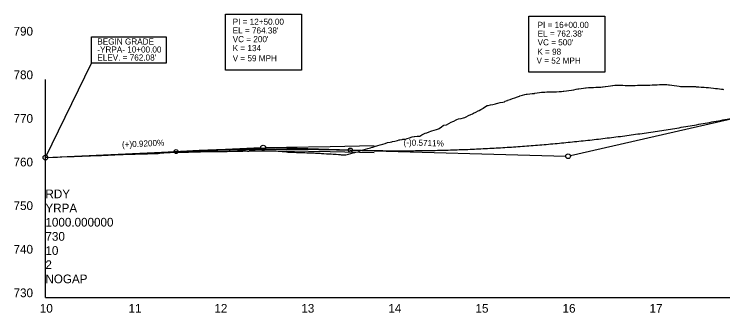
# Model space of a CAD drawing. Extents: x 579185 to 595036, y -53221 to -44640.
# Drawn here: x 579251 to 580065, y -52480 to -52138 of the extents above; entities that cross this region are included whole.
import ezdxf

# ---------------------------------------------------------------- set-up
doc = ezdxf.new("R2010")
doc.units = 0
for name, color, linetype in [('Default', 7, 'Continuous'), ('Exist Profile Cell', 7, 'Continuous'), ('Exist Vertical Profile Ground Line', 7, 'Continuous'), ('Exist Vertical Profile Horizontal Axis Label Major', 7, 'Continuous'), ('Exist Vertical Profile Vertical Axis Label', 7, 'Continuous'), ('Prop Grid Mask', 7, 'Continuous'), ('Prop Vertical Profile Curve Label', 7, 'Continuous'), ('Prop Vertical Profile Grade', 7, 'Continuous'), ('Prop Vertical Profile Grade Label', 7, 'Continuous'), ('Prop VPI Label', 7, 'Continuous')]:
    doc.layers.add(name, color=color, linetype=linetype)

msp = doc.modelspace()

# ---------------------------------------------------------------- linework, layer by layer
at = {"layer": 'Default'}
for points in [[(579287.34, -52302.25), (579314.37, -52300.95), (579364.23, -52298.74), (579414.11, -52296.26), (579464.01, -52293.7), (579513.93, -52291.66), (579563.95, -52290.5), (579614.16, -52289.59), (579664.7, -52288.43)], [(579287.34, -52302.25), (579314.37, -52300.95), (579364.23, -52298.74), (579414.11, -52296.95), (579464.01, -52295.52), (579513.93, -52294.72), (579563.95, -52294.55), (579614.16, -52295.18), (579664.7, -52296.48)]]:
    msp.add_lwpolyline(points, dxfattribs=at)
at = {"layer": 'Exist Profile Cell'}
for q in [(579287.34, -52212.63), (580953.86, -52462.63), (579287.34, -52462.63)]:
    msp.add_line((579287.34, -52462.63), q, dxfattribs=at)
at = {"layer": 'Exist Vertical Profile Ground Line'}
for points in [[(579739.22, -52268.87), (579742.03, -52266.83), (579743.91, -52265.47), (579744.84, -52265.25), (579747.73, -52264.58), (579750.47, -52263.2), (579753.28, -52261.77), (579755.08, -52260.85), (579756.09, -52260.34), (579758.91, -52258.9), (579759.63, -52258.53), (579761.72, -52258.01), (579764.53, -52257.32), (579767.34, -52256.61), (579768.67, -52256.28), (579770.16, -52255.56), (579772.97, -52254.19), (579775.78, -52252.82), (579777.63, -52251.92), (579778.59, -52251.46), (579781.41, -52250.12), (579784.22, -52248.78), (579785.14, -52248.34), (579787.03, -52247.27), (579789.39, -52245.93), (579789.85, -52245.64), (579792.66, -52243.82), (579794.37, -52242.7), (579795.47, -52242.46), (579798.28, -52241.84), (579801.1, -52241.22), (579803.91, -52240.61), (579805.29, -52240.31), (579806.72, -52239.96), (579809.53, -52239.28), (579812.35, -52238.61), (579814.21, -52238.16), (579815.16, -52237.75), (579817.63, -52236.7), (579817.97, -52236.58), (579820.78, -52235.59), (579823.6, -52234.59), (579826.41, -52233.59), (579829.22, -52232.59), (579831.58, -52231.75), (579832.03, -52231.62), (579834.85, -52230.85), (579837.66, -52230.07), (579839.04, -52229.69), (579840.47, -52229.53), (579843.28, -52229.23), (579846.1, -52228.93), (579848.91, -52228.62), (579849.31, -52228.58), (579851.72, -52228.17), (579854.53, -52227.7), (579856.74, -52227.33), (579857.35, -52227.29), (579860.16, -52227.12), (579860.64, -52227.09), (579862.97, -52227.05), (579865.79, -52227), (579868.6, -52226.95), (579869.73, -52226.93), (579871.41, -52226.85), (579874.22, -52226.71), (579877.04, -52226.57), (579877.86, -52226.53), (579879.85, -52226.38), (579881.67, -52226.25), (579882.66, -52226.11), (579885.47, -52225.72), (579888.29, -52225.32), (579891.1, -52224.93), (579893.43, -52224.61), (579893.91, -52224.5), (579896.72, -52223.87), (579898.6, -52223.45), (579899.54, -52223.32), (579902.35, -52222.92), (579905.16, -52222.52), (579907.37, -52222.2), (579907.97, -52222.18), (579910.79, -52222.05), (579913.6, -52221.92), (579916.41, -52221.8), (579919.22, -52221.67), (579922.09, -52221.54), (579924.85, -52221.37), (579926.8, -52221.24), (579927.66, -52221.14), (579930.1, -52220.87), (579930.47, -52220.81), (579933.29, -52220.34), (579936.1, -52219.88), (579938.37, -52219.5), (579938.91, -52219.45), (579940.97, -52219.24), (579941.72, -52219.21), (579942.2, -52219.19), (579944.54, -52219.25)], [(579944.54, -52219.25), (579947.35, -52219.31), (579950.16, -52219.37), (579952.98, -52219.43), (579955.79, -52219.49), (579957.21, -52219.53), (579958.6, -52219.51), (579961.41, -52219.46), (579964.23, -52219.42), (579967.04, -52219.38), (579969.85, -52219.33), (579972.66, -52219.29), (579975.48, -52219.24), (579977.49, -52219.21), (579978.29, -52219.18), (579981.1, -52219.06), (579983.91, -52218.95), (579986.73, -52218.83), (579989.54, -52218.72), (579992.35, -52218.61), (579995.16, -52218.49), (579997.98, -52218.38), (579998.43, -52218.36), (580000.79, -52218.31), (580002.75, -52218.88), (580003.6, -52218.98), (580006.41, -52219.33), (580009.23, -52219.67), (580012.04, -52220.02), (580014.85, -52220.36), (580016.54, -52220.57), (580017.66, -52220.59), (580020.48, -52220.64), (580023.29, -52220.69), (580026.1, -52220.75), (580028.92, -52220.8), (580031.73, -52220.86), (580033.44, -52220.89), (580034.54, -52220.96), (580037.35, -52221.14), (580040.17, -52221.32), (580042.98, -52221.51), (580043.63, -52221.55), (580045.79, -52221.78), (580048.6, -52222.08), (580051.42, -52222.38), (580054.23, -52222.68), (580056.57, -52222.93), (580058.92, -52223.18), (580061.26, -52223.43), (580063.6, -52223.68), (580064.89, -52223.82), (580065.95, -52224.06)], [(579533.43, -52294.64), (579535.78, -52294.63), (579538.12, -52294.62), (579540.46, -52294.61), (579542.81, -52294.6), (579545.15, -52294.6), (579546.87, -52294.6), (579547.5, -52294.59), (579549.84, -52294.55), (579550.71, -52294.53), (579552.18, -52294.61), (579554.53, -52294.74), (579555.83, -52294.81), (579556.87, -52294.92), (579559.21, -52295.17), (579561.56, -52295.43), (579563.9, -52295.69), (579565.66, -52295.89), (579566.25, -52295.91), (579568.59, -52296.01), (579570.93, -52296.1), (579573.35, -52296.21), (579575.62, -52296.27), (579577.96, -52296.34), (579580.31, -52296.41), (579582.65, -52296.48), (579585, -52296.56), (579587.34, -52296.65), (579590.15, -52296.75), (579592.96, -52296.86), (579595.78, -52296.98), (579597.4, -52297.05), (579598.59, -52297.11), (579601.4, -52297.24), (579602.26, -52297.28), (579602.64, -52297.35), (579604.21, -52297.45), (579606.39, -52297.58), (579607.03, -52297.62), (579609.84, -52297.78), (579612.65, -52297.95), (579615.46, -52298.12), (579617.69, -52298.26), (579618.28, -52298.3), (579621.09, -52298.51), (579623.9, -52298.72), (579625.6, -52298.86), (579626.72, -52298.92), (579629.53, -52299.09), (579632.34, -52299.24), (579635.15, -52298.46), (579637.97, -52297.66), (579640.78, -52296.86), (579642.69, -52296.31), (579643.59, -52296.16), (579646.4, -52295.68), (579649.22, -52294.25), (579649.74, -52293.99), (579652.03, -52293.38), (579654.84, -52292.62), (579657.65, -52291.85), (579660.47, -52291.07), (579662.59, -52290.47), (579663.28, -52290.26), (579666.09, -52289.36), (579667.76, -52288.83), (579668.9, -52288.49), (579671.72, -52287.66), (579674.53, -52286.82), (579677.34, -52285.97), (579680.15, -52285.11), (579682.97, -52284.58), (579684.83, -52284.21), (579685.78, -52283.99), (579688.59, -52283.3), (579691.4, -52282.6), (579693.56, -52282.06), (579694.22, -52281.93), (579697.03, -52281.41), (579697.65, -52281.29), (579699.84, -52281.05), (579700.57, -52280.97), (579702.66, -52280.34), (579705.47, -52279.48), (579708.28, -52278.61), (579710.47, -52277.94), (579711.09, -52277.9), (579713.91, -52277.73), (579716.72, -52277.56), (579717.04, -52277.54), (579719.53, -52276.23), (579722.34, -52274.78), (579723.47, -52274.32), (579725.16, -52273.86), (579727.97, -52272.71), (579729.81, -52271.94), (579730.78, -52271.66), (579733.59, -52270.85), (579736.41, -52270.02), (579738.48, -52269.41), (579739.22, -52268.87)], [(579287.34, -52302.25), (579296.71, -52301.82), (579298.51, -52301.73), (579301.13, -52301.62), (579306.09, -52301.43), (579315.46, -52301.07), (579318.71, -52300.95), (579320.15, -52300.89), (579324.84, -52300.71), (579326.21, -52300.66), (579329.53, -52300.53), (579334.21, -52300.36), (579338.96, -52300.18), (579343.59, -52300), (579348.28, -52299.83), (579351.77, -52299.69), (579352.96, -52299.65), (579357.65, -52299.46), (579359.54, -52299.39), (579362.34, -52299.28), (579367.03, -52299.09), (579371.71, -52298.91), (579375.87, -52298.75), (579376.4, -52298.72), (579381.09, -52298.53), (579385.78, -52298.35), (579388.2, -52298.25), (579390.46, -52298.16), (579395.15, -52297.99), (579397.5, -52297.88), (579398.17, -52297.8), (579400.13, -52297.92), (579402.18, -52297.86), (579404.53, -52297.8), (579406.87, -52297.74), (579409.21, -52297.67), (579411.56, -52297.61), (579413.9, -52297.55), (579416.25, -52297.5), (579416.64, -52297.49), (579418.59, -52297.22), (579420.93, -52296.91), (579421.97, -52296.77), (579423.28, -52296.63), (579425.66, -52296.37), (579427.96, -52296.25), (579430.31, -52296.13), (579432.65, -52296.01), (579434.62, -52295.91), (579435, -52295.91), (579437.34, -52295.92), (579439.68, -52295.92), (579442.03, -52295.93), (579443.39, -52295.93), (579444.37, -52295.93), (579446.71, -52295.92), (579449.06, -52295.91), (579449.84, -52295.91), (579451.4, -52295.88), (579453.75, -52295.83), (579456.09, -52295.79), (579458.43, -52295.74), (579459.05, -52295.73), (579460.78, -52295.68), (579463.12, -52295.6), (579465.46, -52295.53), (579467.81, -52295.46), (579469.64, -52295.4), (579470.15, -52295.4), (579472.5, -52295.4), (579474.84, -52295.39), (579477.18, -52295.39), (579479.53, -52295.39), (579481.87, -52295.39), (579484.21, -52295.39), (579486.56, -52295.4), (579486.95, -52295.4), (579489.15, -52295.36), (579491.25, -52295.29), (579493.59, -52295.23), (579493.99, -52295.22), (579495.93, -52295.13), (579498.28, -52295.03), (579500.62, -52294.92), (579502.96, -52294.82), (579505.31, -52294.72), (579507.65, -52294.62), (579510, -52294.52), (579510.55, -52294.5), (579512.34, -52294.54), (579514.68, -52294.61), (579517.03, -52294.67), (579519.37, -52294.73), (579520.4, -52294.76), (579521.71, -52294.31), (579524.26, -52293.54), (579526.4, -52293.94), (579528.75, -52294.38), (579530.22, -52294.66), (579531.09, -52294.65), (579533.43, -52294.64)]]:
    msp.add_lwpolyline(points, dxfattribs=at)
at = {"layer": 'Prop Grid Mask'}
for points in [[(579493.95, -52137.82), (579581.31, -52137.82), (579581.31, -52202), (579493.95, -52202)], [(579842.22, -52140.24), (579929.58, -52140.24), (579929.58, -52204.42), (579842.22, -52204.42)], [(579340.36, -52163.89), (579425.76, -52163.89), (579425.76, -52194.08), (579340.36, -52194.08)]]:
    msp.add_lwpolyline(points, close=True, dxfattribs=at)
at = {"layer": 'Prop Vertical Profile Curve Label'}
msp.add_line((579287.34, -52302.25), (579340.36, -52194.08), dxfattribs=at)
for centre in [(579437.34, -52295.35), (579637.34, -52293.61), (579637.34, -52293.61)]:
    msp.add_circle(centre, 2.25, dxfattribs=at)
at = {"layer": 'Prop Vertical Profile Grade'}
msp.add_line((579287.34, -52302.25), (579437.34, -52295.35), dxfattribs=at)
for points in [[(579637.34, -52293.61), (579647.34, -52293.87), (579657.34, -52294.08), (579667.34, -52294.24), (579677.34, -52294.34), (579687.34, -52294.4), (579697.34, -52294.4), (579707.34, -52294.35), (579717.34, -52294.26), (579727.34, -52294.11), (579737.34, -52293.91), (579747.34, -52293.66), (579757.34, -52293.35), (579767.34, -52293), (579777.34, -52292.6), (579787.34, -52292.14), (579797.34, -52291.63), (579807.34, -52291.08), (579817.34, -52290.47), (579827.34, -52289.81), (579837.34, -52289.1), (579847.34, -52288.33), (579857.34, -52287.52), (579867.34, -52286.65), (579877.34, -52285.74), (579887.34, -52284.77), (579897.34, -52283.75), (579907.34, -52282.68), (579917.34, -52281.56), (579927.34, -52280.39), (579937.34, -52279.17), (579947.34, -52277.9), (579957.34, -52276.57), (579967.34, -52275.2), (579977.34, -52273.77), (579987.34, -52272.29), (579997.34, -52270.76), (580007.34, -52269.18), (580017.34, -52267.55), (580027.34, -52265.87), (580037.34, -52264.13), (580047.34, -52262.35), (580057.34, -52260.51), (580067.34, -52258.63), (580077.34, -52256.69), (580087.34, -52254.7), (580097.34, -52252.66), (580107.34, -52250.57), (580117.34, -52248.42), (580127.34, -52246.23), (580137.34, -52243.98)], [(579437.34, -52295.35), (579441.34, -52295.17), (579445.34, -52295), (579449.34, -52294.83), (579453.34, -52294.66), (579457.34, -52294.51), (579461.34, -52294.36), (579465.34, -52294.21), (579469.34, -52294.07), (579473.34, -52293.94), (579477.34, -52293.81), (579481.34, -52293.69), (579485.34, -52293.57), (579489.34, -52293.46), (579493.34, -52293.36), (579497.34, -52293.26), (579501.34, -52293.17), (579505.34, -52293.09), (579509.34, -52293.01), (579513.34, -52292.93), (579517.34, -52292.87), (579521.34, -52292.8), (579525.34, -52292.75), (579529.34, -52292.7), (579533.34, -52292.65), (579537.34, -52292.62), (579541.34, -52292.58), (579545.34, -52292.56), (579549.34, -52292.54), (579553.34, -52292.52), (579557.34, -52292.52), (579561.34, -52292.51), (579565.34, -52292.52), (579569.34, -52292.53), (579573.34, -52292.54), (579577.34, -52292.57), (579581.34, -52292.59), (579585.34, -52292.63), (579589.34, -52292.67), (579593.34, -52292.71), (579597.34, -52292.76), (579601.34, -52292.82), (579605.34, -52292.89), (579609.34, -52292.95), (579613.34, -52293.03), (579617.34, -52293.11), (579621.34, -52293.2), (579625.34, -52293.29), (579629.34, -52293.39), (579633.34, -52293.5), (579637.34, -52293.61)]]:
    msp.add_spline(points, degree=3, dxfattribs=at)
at = {"layer": 'Prop VPI Label'}
for p, q in [((580137.34, -52243.98), (579890.02, -52300.14)), ((579437.34, -52295.35), (579534.59, -52290.88)), ((579637.34, -52293.61), (579540.09, -52290.83)), ((579637.34, -52293.61), (579884.59, -52300.67))]:
    msp.add_line(p, q, dxfattribs=at)
for centre in [(579537.34, -52290.75), (579287.34, -52302.25), (579887.34, -52300.75)]:
    msp.add_circle(centre, 2.75, dxfattribs=at)

# ---------------------------------------------------------------- texts
at = {"layer": 'Exist Profile Cell'}
for s, p in [('RDY', (579287.34, -52348.88)), ('YRPA', (579287.34, -52365.13)), ('1000.000000', (579287.34, -52381.38)), ('730', (579287.34, -52397.63)), ('10', (579287.34, -52413.88)), ('2', (579287.34, -52430.13)), ('NOGAP', (579287.34, -52446.38))]:
    msp.add_text(s, height=10, dxfattribs=at).set_placement(p)
at = {"layer": 'Exist Vertical Profile Horizontal Axis Label Major'}
for s, p in [('10', (579280.92, -52480.13)), ('11', (579382.76, -52480.13)), ('12', (579481.31, -52480.13)), ('13', (579581.15, -52480.13)), ('14', (579680.99, -52480.13)), ('15', (579781.08, -52480.13)), ('16', (579881.02, -52480.13)), ('17', (579980.88, -52480.13))]:
    msp.add_text(s, height=10, dxfattribs=at).set_placement(p)
at = {"layer": 'Exist Vertical Profile Vertical Axis Label'}
for s, p in [('790', (579250.77, -52162.38)), ('780', (579250.77, -52212.38)), ('770', (579250.77, -52262.38)), ('760', (579250.77, -52312.38)), ('750', (579250.77, -52362.38)), ('740', (579250.77, -52412.38)), ('730', (579250.77, -52462.38))]:
    msp.add_text(s, height=10, dxfattribs=at).set_placement(p)
at = {"layer": 'Prop Vertical Profile Curve Label'}
for s, p in [("VC = 200'", (579502.34, -52169.94)), ("VC = 500'", (579852.34, -52173.57)), ('K = 134', (579502.34, -52180.19)), ('K = 98', (579852.06, -52184.32)), ('V = 59 MPH', (579502.34, -52191.83)), ('V = 52 MPH', (579851.15, -52194.49))]:
    msp.add_text(s, height=7, dxfattribs=at).set_placement(p)
at = {"layer": 'Prop Vertical Profile Grade Label'}
for s, rotation, p in [('(+)0.9200%', 2.63375, (579375.33, -52290.8)), ('(-)0.5711%', 358.36424, (579698.38, -52288.26))]:
    msp.add_text(s, height=7, rotation=rotation, dxfattribs=at).set_placement(p)
at = {"layer": 'Prop VPI Label'}
for s, p in [('PI = 12+50.00', (579502.34, -52149.94)), ('PI = 16+00.00', (579852.34, -52153.57)), ("EL = 764.38'", (579502.34, -52159.94)), ("EL = 762.38'", (579852.34, -52163.57)), ('BEGIN GRADE', (579346.92, -52172.65)), ('-YRPA- 10+00.00', (579346.92, -52181.82)), ("ELEV. = 762.08'", (579346.92, -52191))]:
    msp.add_text(s, height=7, dxfattribs=at).set_placement(p)

doc.saveas('drawing.dxf')
